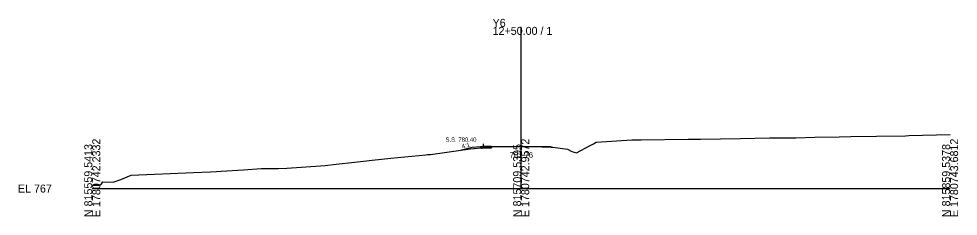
# Model space of a CAD drawing. Extents: x -26 to 1603, y -10 to 6024.
# Drawn here: x -25.7 to 302.8, y 3490.3 to 3559.5 of the extents above; entities that cross this region are included whole.
import ezdxf

# ---------------------------------------------------------------- set-up
doc = ezdxf.new("R2010")
doc.units = 0
for name, color, linetype in [('Exist Cross Section Cell', 7, 'Continuous'), ('Exist XS Center Line Elevation Label', 7, 'Continuous'), ('Exist XS Ground Line', 7, 'Continuous'), ('Prop XS Ditch Slope Text', 7, 'Continuous'), ('Prop XS Dump Level', 7, 'Continuous'), ('Prop XS Earthwork Shape', 7, 'Continuous'), ('Prop XS EOT Tick Mark', 7, 'Continuous'), ('Prop XS Finish Grade', 7, 'Continuous'), ('Prop XS Finish Grade Earthwork', 7, 'Continuous'), ('Prop XS Finish Grade Pavement', 7, 'Continuous'), ('Prop XS Pvmt Edge Slope', 7, 'Continuous'), ('Prop XS SS Elevation Text', 7, 'Continuous'), ('Prop XS Subgrade Earthwork', 7, 'Continuous')]:
    doc.layers.add(name, color=color, linetype=linetype)

msp = doc.modelspace()

# ---------------------------------------------------------------- linework, layer by layer
at = {"layer": 'Exist Cross Section Cell'}
for p, q in [((150, 3500), (150, 3556.64)), ((0, 3500), (150, 3500)), ((150, 3500), (300, 3500))]:
    msp.add_line(p, q, dxfattribs=at)
at = {"layer": 'Exist XS Ground Line'}
for p, q in [((285.61, 3518.53), (300, 3518.88)), ((174.15, 3515.12), (175.31, 3515.67)), ((175.31, 3515.67), (176.25, 3516.27)), ((176.25, 3516.27), (188.67, 3517.02)), ((188.67, 3517.02), (189.16, 3517.03)), ((189.16, 3517.03), (191.99, 3517.07)), ((191.99, 3517.07), (208.35, 3517.27)), ((208.35, 3517.27), (210.19, 3517.27)), ((210.19, 3517.27), (212.72, 3517.33)), ((212.72, 3517.33), (226.74, 3517.59)), ((226.74, 3517.59), (236.8, 3517.72)), ((236.8, 3517.72), (246.09, 3517.78)), ((246.09, 3517.78), (252.75, 3517.95)), ((252.75, 3517.95), (261.25, 3518.13)), ((261.25, 3518.13), (265.27, 3518.23)), ((265.27, 3518.23), (274.27, 3518.41)), ((274.27, 3518.41), (284.45, 3518.5)), ((284.45, 3518.5), (285.61, 3518.53)), ((118.27, 3511.99), (127.25, 3513.19)), ((127.25, 3513.19), (129.64, 3513.53)), ((129.64, 3513.53), (132.23, 3513.94)), ((132.23, 3513.94), (139.49, 3514.6)), ((139.49, 3514.6), (149.97, 3514.76)), ((149.97, 3514.76), (157.28, 3514.61)), ((157.28, 3514.61), (160.44, 3514.55)), ((160.44, 3514.55), (161.05, 3514.46)), ((161.05, 3514.46), (166.2, 3513.8)), ((166.2, 3513.8), (167.7, 3512.99)), ((167.7, 3512.99), (169.35, 3512.51)), ((169.35, 3512.51), (174.15, 3515.12)), ((85.3, 3508.52), (91.71, 3509.24)), ((91.71, 3509.24), (94.89, 3509.61)), ((94.89, 3509.61), (97.88, 3509.95)), ((97.88, 3509.95), (104.36, 3510.68)), ((104.36, 3510.68), (116.63, 3511.83)), ((116.63, 3511.83), (117.26, 3511.9)), ((117.26, 3511.9), (118.27, 3511.99)), ((13.61, 3504.69), (35.43, 3505.63)), ((35.43, 3505.63), (41.41, 3505.91)), ((41.41, 3505.91), (43.48, 3505.96)), ((43.48, 3505.96), (45.11, 3506.09)), ((45.11, 3506.09), (52.86, 3506.57)), ((52.86, 3506.57), (59.12, 3507)), ((59.12, 3507), (65.15, 3507.04)), ((65.15, 3507.04), (68.01, 3507.12)), ((68.01, 3507.12), (81.41, 3508.12)), ((81.41, 3508.12), (85.3, 3508.52)), ((3.29, 3501.65), (3.7, 3502.32)), ((3.7, 3502.32), (7.3, 3502.24)), ((7.3, 3502.24), (9.98, 3503.23)), ((9.98, 3503.23), (13.61, 3504.69)), ((0, 3501.15), (0.9, 3501.18)), ((0.9, 3501.18), (2.54, 3501.23)), ((2.54, 3501.23), (3.29, 3501.65))]:
    msp.add_line(p, q, dxfattribs=at)
at = {"layer": 'Prop XS Earthwork Shape'}
for points in [[(136.03, 3514.28), (135.72, 3514.6), (132.82, 3514.38), (129.09, 3513.45), (129.64, 3513.53), (132.23, 3513.94)], [(136.03, 3514.28), (139.49, 3514.6), (139.49, 3514.14), (136.23, 3514.09)]]:
    msp.add_lwpolyline(points, close=True, dxfattribs=at)
at = {"layer": 'Prop XS EOT Tick Mark'}
msp.add_line((136.82, 3514.68), (136.82, 3515.68), dxfattribs=at)
at = {"layer": 'Prop XS Finish Grade'}
msp.add_line((136.82, 3514.68), (135.72, 3514.6), dxfattribs=at)
at = {"layer": 'Prop XS Finish Grade Earthwork'}
for p, q in [((132.82, 3514.38), (129.09, 3513.45)), ((135.72, 3514.6), (132.82, 3514.38))]:
    msp.add_line(p, q, dxfattribs=at)
at = {"layer": 'Prop XS Finish Grade Pavement'}
for p, q in [((139.49, 3514.73), (136.82, 3514.68)), ((139.49, 3514.73), (149.97, 3514.89)), ((139.49, 3514.73), (139.5, 3514.6)), ((149.97, 3514.89), (157.29, 3514.73)), ((157.29, 3514.73), (160.45, 3514.68))]:
    msp.add_line(p, q, dxfattribs=at)
at = {"layer": 'Prop XS Pvmt Edge Slope'}
msp.add_line((136.82, 3514.68), (136.23, 3514.09), dxfattribs=at)
at = {"layer": 'Prop XS Subgrade Earthwork'}
for p, q in [((136.23, 3514.09), (135.72, 3514.6)), ((139.49, 3514.14), (136.23, 3514.09)), ((139.49, 3514.14), (139.49, 3514.6))]:
    msp.add_line(p, q, dxfattribs=at)

# ---------------------------------------------------------------- texts
at = {"layer": 'Exist Cross Section Cell'}
for s, p in [('Y6', (140, 3556.64)), ('12+50.00 / 1', (140, 3553.84)), ('EL 767', (-26, 3498.6))]:
    msp.add_text(s, height=2.8, dxfattribs=at).set_placement(p)
for s, p in [('N 815559.5413', (0, 3490)), ('E 1780742.2332', (2.8, 3490)), ('N 815709.5395', (150, 3490)), ('E 1780742.9572', (152.8, 3490)), ('N 815859.5378', (300, 3490)), ('E 1780743.6812', (302.8, 3490))]:
    msp.add_text(s, height=2.8, rotation=90, dxfattribs=at).set_placement(p)
at = {"layer": 'Exist XS Center Line Elevation Label'}
msp.add_text('781.76', height=2, dxfattribs=at).set_placement((145.97, 3510.76))
at = {"layer": 'Prop XS Ditch Slope Text'}
msp.add_text('4:1', height=1.5, rotation=14.0362, dxfattribs=at).set_placement((129.38, 3514.01))
at = {"layer": 'Prop XS Dump Level'}
for s, height, p in [('Case1', 0.04, (132.82, 3514.34)), ('Eop', 0.3, (139.49, 3514.3))]:
    msp.add_text(s, height=height, dxfattribs=at).set_placement(p)
at = {"layer": 'Prop XS SS Elevation Text'}
msp.add_text('S.S. 780.40', height=1.5, dxfattribs=at).set_placement((123.54, 3516.4))

doc.saveas('drawing.dxf')
